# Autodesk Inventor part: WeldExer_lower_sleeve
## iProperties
Shininess: 64.0
Length Units: 11269
Angle Units: 11279
Time Units: 11290
Mass Units: 11286
Length Display Precision: 3
Angle Display Precision: 2
Compacted: True
Part Number: WeldExer_lower_sleeve
Document SubType Name: Modeling
Created: 2003-07
Designer: Ronald Myers
Manufacturer: Standard
Standards Organization: Custom
Stock Number: WeldExer_lower_sleeve
Density: 1 g/cm^3
Density: 0.0
Volumn: 0.0
Area: 0.0
PropertySet Name: Model Information
Control State: 0
Master: False
Checked Out: False
Author: Ronald Myers
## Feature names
1. Extrusion1
2. Extrusion2
